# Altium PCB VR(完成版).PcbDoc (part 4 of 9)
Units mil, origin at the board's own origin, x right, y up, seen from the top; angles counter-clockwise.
Board outline 2839.68 x 2020.7 mil, 6 copper layers (TOP, GND02, SIN03, SIN04, PWR05, BOTTOM); 494 components, 404 nets, 7124 pads, 1123 vias.
Unrouted connection lines stored in the file: 10.
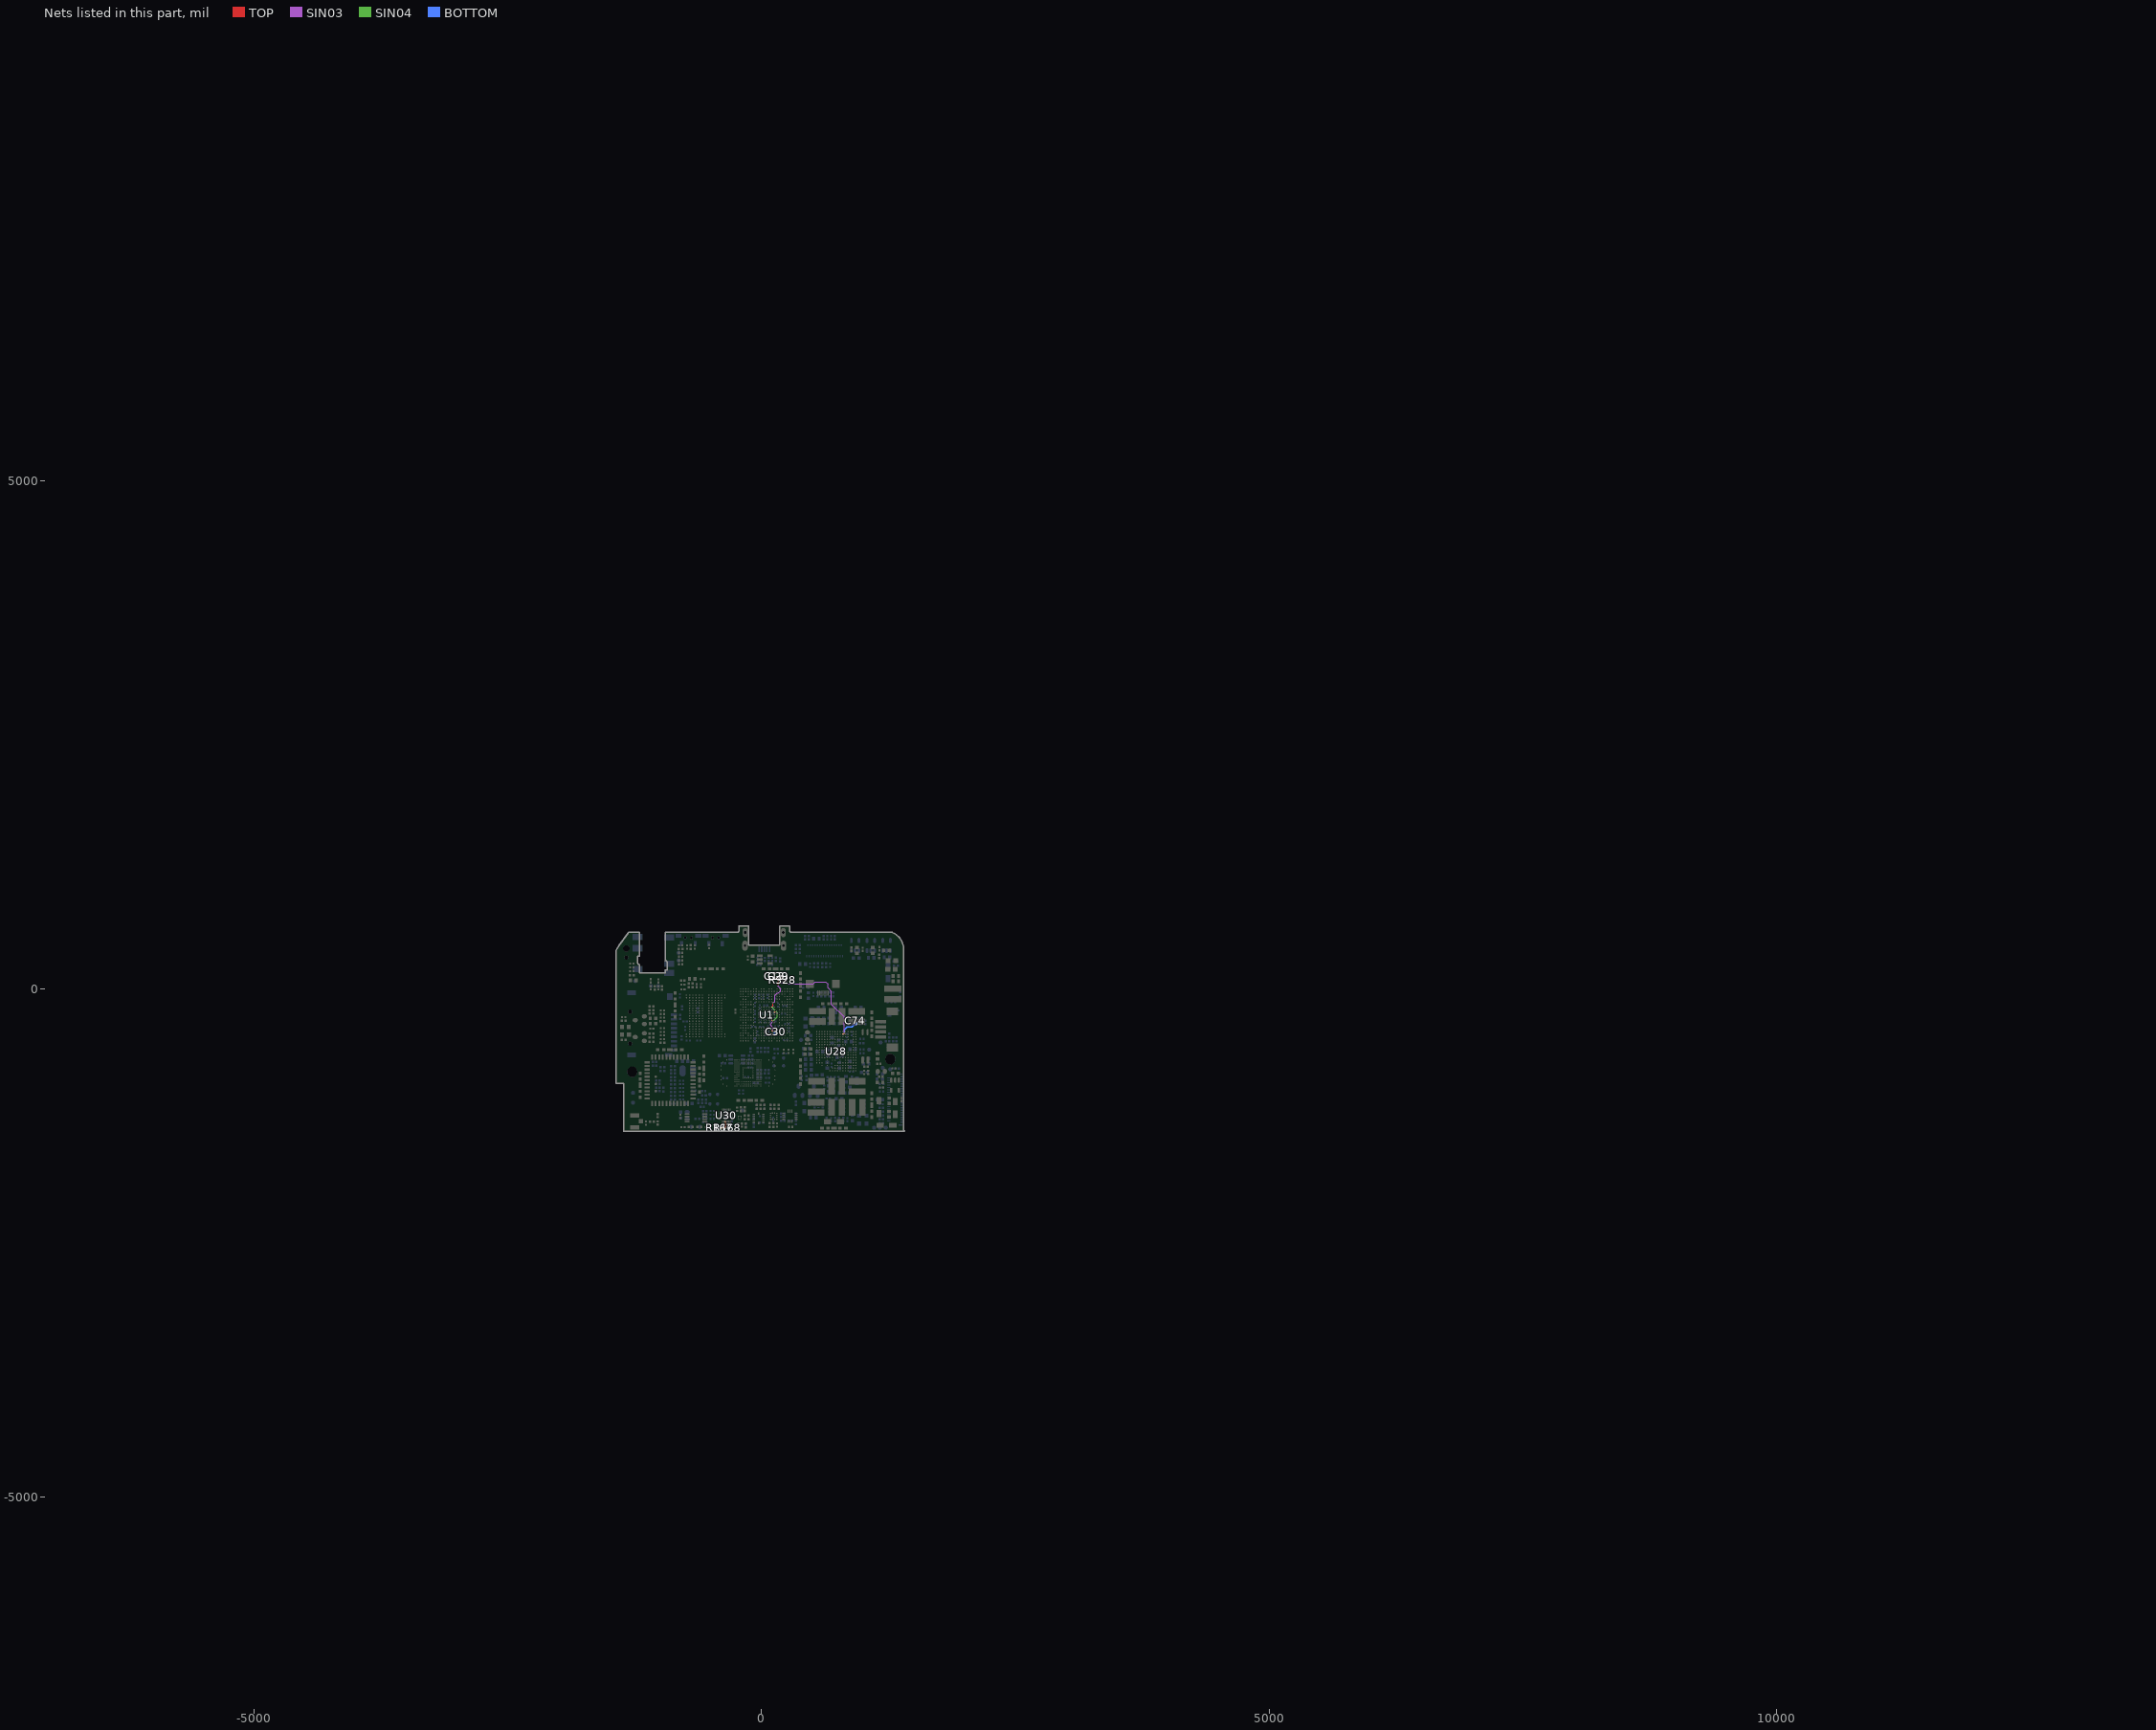
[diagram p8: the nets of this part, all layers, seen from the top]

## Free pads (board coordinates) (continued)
  round 6 on Drill Drawing: 1(6975.12,-691.2) 1(6975.12,-691.2) 1(6975.12,-656.2) 1(6995.12,-691.2) 1(7002.62,-691.2) 1(7007.12,-678.95) 1(7015.12,-656.2) 1(7015.12,-656.2) 1(7023.12,-678.95) 1(7027.62,-691.2) 1(7035.12,-656.2) 1(7045.12,-691.2) 1(7045.12,-675.45) 1(7045.12,-675.45) 1(7045.12,-675.45) 1(7055.12,-656.2) 1(7059.93,-2776.59) 1(7059.93,-2776.59) 1(7059.93,-2741.59) 1(7065.12,-691.2) 1(7065.12,-691.2) 1(7065.12,-673.12) 1(7065.12,-656.2) 1(7065.12,-656.2) 1(7077.12,-673.12) 1(7079.93,-2776.59) 1(7085.12,-691.2) 1(7085.12,-656.2) 1(7087.43,-2776.59) 1(7091.93,-2764.34) 1(7095.12,-691.2) 1(7095.12,-674.28) 1(7095.12,-656.2) 1(7095.12,-656.2) 1(7099.93,-2741.59) 1(7099.93,-2741.59) 1(7107.62,-674.28) 1(7107.62,-674.28) 1(7107.62,-674.28) 1(7107.62,-656.2) 1(7107.62,-656.2) 1(7107.93,-2764.34) 1(7111.12,-672.53) 1(7111.12,-672.53) 1(7111.62,-657.95) 1(7111.62,-657.95) 1(7112.43,-2776.59) 1(7114.12,-669.62) 1(7114.12,-669.62) 1(7114.12,-660.28) 1(7114.12,-660.28) 1(7115.12,-691.2) 1(7115.12,-664.95) 1(7115.12,-664.95) 1(7119.93,-2741.59) 1(7129.93,-2776.59) 1(7129.93,-2760.84) 1(7129.93,-2760.84) 1(7129.93,-2760.84) 1(7139.93,-2741.59) 1(7146.46,2469.67) 1(7146.46,2689.67) 1(7146.46,2909.67) 1(7146.46,3129.67) 1(7146.46,3349.67) 1(7149.93,-2776.59) 1(7149.93,-2776.59) 1(7149.93,-2758.51) 1(7149.93,-2741.59) 1(7149.93,-2741.59) 1(7161.93,-2758.51) 1(7169.93,-2776.59) 1(7169.93,-2741.59) 1(7179.93,-2776.59) 1(7179.93,-2759.67) 1(7179.93,-2741.59) 1(7179.93,-2741.59) 1(7192.43,-2759.67) 1(7192.43,-2759.67) 1(7192.43,-2759.67) 1(7192.43,-2741.59) 1(7192.43,-2741.59) 1(7195.93,-2757.92) 1(7195.93,-2757.92) 1(7196.43,-2743.34) 1(7196.43,-2743.34) 1(7198.93,-2755.01) 1(7198.93,-2755.01) 1(7198.93,-2745.67) 1(7198.93,-2745.67) 1(7199.93,-2776.59) 1(7199.93,-2750.34) 1(7199.93,-2750.34) 1(7226.46,2449.67) 1(7226.46,2449.67) 1(7226.46,2489.67) 1(7226.46,2489.67) 1(7226.46,2669.67) 1(7226.46,2669.67) 1(7226.46,2709.67) 1(7226.46,2709.67) 1(7226.46,2889.67) 1(7226.46,2889.67) 1(7226.46,2929.67) 1(7226.46,2929.67) 1(7226.46,3109.67) 1(7226.46,3109.67) 1(7226.46,3149.67) 1(7226.46,3149.67) 1(7226.46,3329.67) 1(7226.46,3329.67) 1(7226.46,3369.67) 1(7226.46,3369.67) 1(7281.46,2469.67) 1(7281.46,2469.67) 1(7281.46,2469.67) 1(7281.46,2689.67) 1(7281.46,2689.67) 1(7281.46,2689.67) 1(7281.46,2909.67) 1(7281.46,2909.67) 1(7281.46,2909.67) 1(7281.46,3129.67) 1(7281.46,3129.67) 1(7281.46,3129.67) 1(7281.46,3349.67) 1(7281.46,3349.67) 1(7281.46,3349.67) 1(7376.96,2434.88) 1(7376.96,2484.88) 1(7376.96,2654.56) 1(7376.96,2704.56) 1(7376.96,2874.25) 1(7376.96,2924.25) 1(7376.96,3093.93) 1(7376.96,3143.93) 1(7376.96,3313.62) 1(7376.96,3363.62) 1(7411.96,2419.88) 1(7411.96,2639.56) 1(7411.96,2859.25) 1(7411.96,3078.93) 1(7411.96,3298.62) 1(7416.96,2524.88) 1(7416.96,2744.56) 1(7416.96,2964.25) 1(7416.96,3183.93) 1(7416.96,3403.62) 1(7449.67,-657.23) 1(7456.67,-692.23) 1(7456.67,-692.23) 1(7461.96,2419.88) 1(7461.96,2639.56) 1(7461.96,2859.25) 1(7461.96,3078.93) 1(7461.96,3298.62) 1(7464.67,-657.23) 1(7464.67,-657.23) 1(7466.96,2524.88) 1(7466.96,2744.56) 1(7466.96,2964.25) 1(7466.96,3183.93) 1(7466.96,3403.62) 1(7472.67,-692.23) 1(7472.67,-692.23) 1(7479.67,-657.23) 1(7484.46,-2732.92) 1(7488.67,-692.23) 1(7488.67,-657.23) 1(7491.46,-2767.92) 1(7491.46,-2767.92) 1(7494.67,-692.23) 1(7494.67,-657.23) 1(7499.46,-2732.92) 1(7499.46,-2732.92) 1(7500.67,-692.23) 1(7500.67,-657.23) 1(7507.46,-2767.92) 1(7507.46,-2767.92) 1(7511.96,2419.88) 1(7511.96,2639.56) 1(7511.96,2859.25) 1(7511.96,3078.93) 1(7511.96,3298.62) 1(7513.67,-692.23) 1(7513.67,-692.23) 1(7513.67,-657.23) 1(7513.67,-657.23) 1(7514.46,-2732.92) 1(7516.96,2524.88) 1(7516.96,2744.56) 1(7516.96,2964.25) 1(7516.96,3183.93) 1(7516.96,3403.62) 1(7523.46,-2767.92) 1(7523.46,-2732.92) 1(7523.67,-692.23) 1(7523.67,-692.23) 1(7523.67,-657.23) 1(7523.67,-657.23) 1(7527.67,-690.48) 1(7527.67,-690.48) 1(7527.67,-658.98) 1(7527.67,-658.98) 1(7529.46,-2767.92) 1(7529.46,-2732.92) 1(7530.67,-688.15) 1(7530.67,-688.15) 1(7530.67,-661.31) 1(7530.67,-661.31) 1(7533.17,-684.65) 1(7533.17,-684.65) 1(7533.17,-664.81) 1(7533.17,-664.81) 1(7535.17,-680.56) 1(7535.17,-680.56) 1(7535.17,-668.9) 1(7535.17,-668.9) 1(7535.46,-2767.92) 1(7535.46,-2732.92) 1(7535.67,-674.73) 1(7535.67,-674.73) 1(7543.17,-657.23) 1(7548.46,-2767.92) 1(7548.46,-2767.92) 1(7548.46,-2732.92) 1(7548.46,-2732.92) 1(7554.67,-692.23) 1(7554.67,-657.23) 1(7558.46,-2767.92) 1(7558.46,-2767.92) 1(7558.46,-2732.92) 1(7558.46,-2732.92) 1(7562.46,-2766.17) 1(7562.46,-2766.17) 1(7562.46,-2734.67) 1(7562.46,-2734.67) 1(7565.46,-2763.84) 1(7565.46,-2763.84) 1(7565.46,-2737) 1(7565.46,-2737) 1(7566.17,-657.23) 1(7566.96,2524.88) 1(7566.96,2744.56) 1(7566.96,2964.25) 1(7566.96,3183.93) 1(7566.96,3403.62) 1(7567.96,-2760.34) 1(7567.96,-2760.34) 1(7567.96,-2740.5) 1(7567.96,-2740.5) 1(7569.96,-2756.25) 1(7569.96,-2756.25) 1(7569.96,-2744.59) 1(7569.96,-2744.59) 1(7570.46,-2750.42) 1(7570.46,-2750.42) 1(7574.17,-692.23) 1(7574.17,-674.73) 1(7574.17,-657.23) 1(7577.96,-2732.92) 1(7589.46,-2767.92) 1(7589.46,-2732.92) 1(7595.17,-692.23) 1(7595.17,-674.73) 1(7595.17,-657.23) 1(7600.96,-2732.92) 1(7608.96,-2767.92) 1(7608.96,-2750.42) 1(7608.96,-2732.92) 1(7616.96,2524.88) 1(7616.96,2744.56) 1(7616.96,2964.25) 1(7616.96,3183.93) 1(7616.96,3403.62) 1(7629.96,-2767.92) 1(7629.96,-2750.42) 1(7629.96,-2732.92) 1(7681.98,-684.06) 1(7681.98,-684.06) 1(7681.98,-660.73) 1(7681.98,-660.73) 1(7684.48,-689.89) 1(7684.48,-689.89) 1(7684.48,-654.89) 1(7684.48,-654.89) 1(7689.46,-2767.92) 1(7689.46,-2767.92) 1(7689.46,-2744.59) 1(7689.46,-2744.59) 1(7689.48,-695.73) 1(7689.48,-649.06) 1(7691.96,-2773.75) 1(7691.96,-2773.75) 1(7691.96,-2738.75) 1(7691.96,-2738.75) 1(7696.96,-2779.59) 1(7696.96,-2732.92) 1(7706.98,-684.06) 1(7706.98,-667.14) 1(7706.98,-660.73) 1(7708.48,-664.23) 1(7708.48,-664.23) 1(7710.98,-661.89) 1(7710.98,-661.89) 1(7714.46,-2767.92) 1(7714.46,-2751) 1(7714.46,-2744.59) 1(7714.48,-660.73) 1(7714.48,-660.73) 1(7715.96,-2748.09) 1(7715.96,-2748.09) 1(7717.98,-661.89) 1(7717.98,-661.89) 1(7718.46,-2745.75) 1(7718.46,-2745.75) 1(7720.48,-664.23) 1(7720.48,-664.23) 1(7721.96,-2744.59) 1(7721.96,-2744.59) 1(7721.98,-684.06) 1(7721.98,-667.14) 1(7721.98,-667.14) 1(7721.98,-667.14) 1(7723.48,-664.23) 1(7723.48,-664.23) 1(7725.46,-2745.75) 1(7725.46,-2745.75) 1(7725.98,-661.89) 1(7725.98,-661.89) 1(7727.96,-2748.09) 1(7727.96,-2748.09) 1(7729.46,-2767.92) 1(7729.46,-2751) 1(7729.46,-2751) 1(7729.46,-2751) 1(7729.48,-660.73) 1(7729.48,-660.73) 1(7730.96,-2748.09) 1(7730.96,-2748.09) 1(7732.98,-661.89) 1(7732.98,-661.89) 1(7733.46,-2745.75) 1(7733.46,-2745.75) 1(7735.48,-664.23) 1(7735.48,-664.23) 1(7736.96,-2744.59) 1(7736.96,-2744.59) 1(7736.98,-684.06) 1(7736.98,-667.73) 1(7736.98,-667.73) 1(7740.46,-2745.75) 1(7740.46,-2745.75) 1(7742.96,-2748.09) 1(7742.96,-2748.09) 1(7744.46,-2767.92) 1(7744.46,-2751.59) 1(7744.46,-2751.59) 1(7750.98,-650.81) 1(7750.98,-650.81) 1(7750.98,-649.64) 1(7750.98,-649.64) 1(7751.98,-684.06) 1(7751.98,-660.73) 1(7751.98,-651.39) 1(7751.98,-651.39) 1(7751.98,-649.06) 1(7751.98,-649.06) 1(7752.98,-650.81) 1(7752.98,-650.81) 1(7752.98,-649.64) 1(7752.98,-649.64) 1(7758.46,-2734.67) 1(7758.46,-2734.67) 1(7758.46,-2733.5) 1(7758.46,-2733.5) 1(7759.46,-2767.92) 1(7759.46,-2744.59) 1(7759.46,-2735.25) 1(7759.46,-2735.25) 1(7759.46,-2732.92) 1(7759.46,-2732.92) 1(7760.46,-2734.67) 1(7760.46,-2734.67) 1(7760.46,-2733.5) 1(7760.46,-2733.5) 1(7781.98,-684.06) 1(7781.98,-649.06) 1(7789.46,-2767.92) 1(7789.46,-2732.92) 1(7814.48,-695.73) 1(7814.48,-649.06) 1(7819.48,-689.89) 1(7819.48,-689.89) 1(7819.48,-654.89) 1(7819.48,-654.89) 1(7821.96,-2779.59) 1(7821.96,-2732.92) 1(7821.98,-684.06) 1(7821.98,-684.06) 1(7821.98,-660.73) 1(7821.98,-660.73) 1(7826.96,-2773.75) 1(7826.96,-2773.75) 1(7826.96,-2738.75) 1(7826.96,-2738.75) 1(7829.46,-2767.92) 1(7829.46,-2767.92) 1(7829.46,-2744.59) 1(7829.46,-2744.59) 1(7861.81,3928.11) 1(7861.81,3928.11) 1(7861.81,3991.11) 1(7865.98,3911.11) 1(7893.15,3928.11) 1(7920.9,3928.11) 1(7927.95,3950.16) 1(7940.48,3991.11) 1(7940.48,3991.11) 1(7953.01,3950.16) 1(7960.06,3928.11) 1(7983.53,3832.51) 1(7986.66,3871.36) 1(7986.66,3871.36) 1(7987.81,3991.11) 1(7988.23,3878.71) 1(7988.23,3878.71) 1(7989.01,3864.01) 1(7989.01,3864.01) 1(7989.8,3827.26) 1(7989.8,3827.26) 1(7992.15,3883.96) 1(7992.15,3883.96) 1(7994.5,3859.81) 1(7994.5,3859.81) 1(7996.85,3824.11) 1(7996.85,3824.11) 1(7997.63,3887.11) 1(7997.63,3887.11) 1(8003.11,3824.11) 1(8003.11,3824.11) 1(8003.11,3887.11) 1(8003.11,3887.11) 1(8003.48,3928.11) 1(8003.48,3956.46) 1(8003.48,3956.46) 1(8003.48,3956.46) 1(8003.9,3857.71) 1(8003.9,3857.71) 1(8008.6,3885.01) 1(8008.6,3885.01) 1(8009.38,3827.26) 1(8009.38,3827.26) 1(8010.95,3853.51) 1(8010.95,3853.51) 1(8013.3,3879.76) 1(8014.08,3832.51) 1(8014.08,3832.51) 1(8014.86,3847.21) 1(8014.86,3847.21) 1(8016.43,3839.86) 1(8016.43,3839.86) 1(8019.15,3991.11) 1(8027.41,-686.86) 1(8027.41,-651.86) 1(8033.41,-686.86) 1(8033.41,-651.86) 1(8039.41,-686.86) 1(8039.41,-651.86) 1(8043.4,3852.46) 1(8043.4,3852.46) 1(8044.18,3861.91) 1(8044.18,3861.91) 1(8044.96,3843.01) 1(8044.96,3843.01) 1(8047.31,3836.71) 1(8047.31,3836.71) 1(8047.31,3872.41) 1(8047.31,3872.41) 1(8050.41,-686.86) 1(8050.41,-651.86) 1(8050.41,-651.86) 1(8050.81,3928.11) 1(8050.81,3928.11) 1(8050.81,3960.66) 1(8050.81,3991.11) 1(8050.81,3991.11) 1(8051.23,3878.71) 1(8051.23,3878.71) 1(8052.01,3830.41) 1(8052.01,3830.41) 1(8056.71,3883.96) 1(8056.71,3883.96) 1(8057.5,3826.21) 1(8057.5,3826.21) 1(8062.98,3824.11) 1(8062.98,3824.11) 1(8063.41,-681.03) 1(8063.41,-681.03) 1(8063.7,2172.55) 1(8063.7,2172.55) 1(8063.7,2206.15) 1(8063.7,2235.55) 1(8063.7,2235.55) 1(8063.76,3887.11) 1(8063.76,3887.11) 1(8068.46,3824.11) 1(8068.46,3824.11) 1(8069.61,3960.66) 1(8070.03,3887.11) 1(8070.03,3887.11) 1(8073.95,3826.21) 1(8073.95,3826.21) 1(8075.51,3885.01) 1(8075.51,3885.01) 1(8076.41,-686.86) 1(8076.41,-651.86) 1(8076.41,-651.86) 1(8077.71,-2776.98) 1(8077.71,-2741.98) 1(8078.65,3829.36) 1(8078.65,3829.36) 1(8080.21,3881.86) 1(8082.15,3928.11) 1(8082.15,3991.11) 1(8082.56,3833.56) 1(8083.41,-686.86) 1(8083.41,-672.28) 1(8083.41,-651.86) 1(8083.41,-651.86) 1(8083.71,-2776.98) 1(8083.71,-2741.98) 1(8084.85,2235.55) 1(8084.85,2235.55) 1(8087.99,2206.15) 1(8087.99,2206.15) 1(8087.99,2206.15) 1(8089.55,2172.55) 1(8089.55,2172.55) 1(8089.71,-2776.98) 1(8089.71,-2741.98) 1(8090.34,2232.4) 1(8090.34,2232.4) 1(8091.12,2209.3) 1(8091.12,2209.3) 1(8093.47,2204.05) 1(8093.47,2204.05) 1(8093.47,2214.55) 1(8093.47,2214.55) 1(8093.47,2228.2) 1(8093.47,2228.2) 1(8095.04,2176.75) 1(8095.04,2176.75) 1(8095.04,2221.9) 1(8095.04,2221.9) 1(8095.41,-672.28) 1(8095.41,-672.28) 1(8095.41,-651.86) 1(8095.41,-651.86) 1(8098.17,2183.05) 1(8098.17,2183.05) 1(8098.17,2197.75) 1(8098.17,2197.75) 1(8099.41,-653.61) 1(8099.41,-653.61) 1(8099.74,2190.4) 1(8099.74,2190.4) 1(8099.91,-670.53) 1(8099.91,-670.53) 1(8100.71,-2776.98) 1(8100.71,-2741.98) 1(8100.71,-2741.98) 1(8102.41,-667.03) 1(8102.41,-667.03) 1(8102.41,-657.69) 1(8102.41,-657.69) 1(8103.41,-662.36) 1(8103.41,-662.36) 1(8106.4,3824.11) 1(8110.51,3638.56) 1(8113.41,-686.86) 1(8113.41,-686.86) 1(8113.41,-668.78) 1(8113.41,-651.86) 1(8113.41,-651.86) 1(8113.45,3846.16) 1(8113.71,-2771.15) 1(8113.71,-2771.15) 1(8113.81,3928.11) 1(8113.81,3958.56) 1(8113.81,3991.11) 1(8113.81,3991.11) 1(8123.57,2199.85) 1(8123.57,2199.85) 1(8123.57,2208.25) 1(8123.57,2208.25) 1(8125.14,2191.45) 1(8125.14,2191.45) 1(8125.14,2216.65) 1(8125.14,2216.65) 1(8125.42,-668.78) 1(8125.98,3887.11) 1(8125.98,3887.11) 1(8126.71,-2776.98) 1(8126.71,-2741.98) 1(8126.71,-2741.98) 1(8128.27,2184.1) 1(8128.27,2184.1) 1(8128.27,2224) 1(8128.27,2224) 1(8128.53,3575.56) 1(8128.53,3638.56) 1(8132.97,2177.8) 1(8132.97,2177.8) 1(8132.97,2230.3) 1(8132.97,2230.3) 1(8133.4,3958.56) 1(8133.4,3958.56) 1(8133.4,3958.56) 1(8133.4,3991.11) 1(8133.4,3991.11) 1(8133.42,-686.86) 1(8133.42,-651.86) 1(8133.71,-2776.98) 1(8133.71,-2762.4) 1(8133.71,-2741.98) 1(8133.71,-2741.98) 1(8138.45,2173.6) 1(8138.45,2173.6) 1(8138.45,2234.5) 1(8138.45,2234.5) 1(8138.51,3846.16) 1(8138.88,3961.71) 1(8138.88,3961.71) 1(8139.66,3987.96) 1(8139.66,3987.96) 1(8142.42,-686.86) 1(8142.42,-686.86) 1(8142.42,-651.86) 1(8142.42,-651.86) 1(8143.58,3966.96) 1(8143.58,3966.96) 1(8143.58,3983.76) 1(8143.58,3983.76) 1(8144.72,2172.55) 1(8144.72,2172.55) 1(8144.72,2235.55) 1(8144.72,2235.55) 1(8145.15,3928.11) 1(8145.15,3975.36) 1(8145.15,3975.36) 1(8145.56,3824.11) 1(8145.71,-2762.4) 1(8145.71,-2762.4) 1(8145.71,-2741.98) 1(8145.71,-2741.98) 1(8146.55,3638.56) 1(8149.71,-2743.73) 1(8149.71,-2743.73) 1(8150.21,-2760.65) 1(8150.21,-2760.65) 1(8150.99,2173.6) 1(8150.99,2173.6) 1(8150.99,2234.5) 1(8150.99,2234.5) 1(8152.42,-686.86) 1(8152.42,-686.86) 1(8152.42,-651.86) 1(8152.42,-651.86) 1(8152.71,-2757.15) 1(8152.71,-2757.15) 1(8152.71,-2747.81) 1(8152.71,-2747.81) 1(8153.71,-2752.48) 1(8153.71,-2752.48) 1(8156.42,-685.11) 1(8156.42,-685.11) 1(8156.42,-653.61) 1(8156.42,-653.61) 1(8156.47,2177.8) 1(8156.47,2177.8) 1(8156.47,2230.3) 1(8156.47,2230.3) 1(8159.42,-682.78) 1(8159.42,-682.78) 1(8159.42,-655.94) 1(8159.42,-655.94) 1(8161.17,2184.1) 1(8161.17,2184.1) 1(8161.17,2224) 1(8161.17,2224) 1(8161.92,-679.28) 1(8161.92,-679.28) 1(8161.92,-659.44) 1(8161.92,-659.44) 1(8163.71,-2776.98) 1(8163.71,-2776.98) 1(8163.71,-2758.9) 1(8163.71,-2741.98) 1(8163.71,-2741.98) 1(8163.92,-675.19) 1(8163.92,-675.19) 1(8163.92,-663.53) 1(8163.92,-663.53) 1(8164.3,2191.45) 1(8164.3,2191.45) 1(8164.3,2216.65) 1(8164.3,2216.65) 1(8164.42,-669.36) 1(8164.42,-669.36) 1(8165.87,2199.85) 1(8165.87,2199.85) 1(8165.87,2208.25) 1(8165.87,2208.25) 1(8170.38,3602.86) 1(8170.38,3602.86) 1(8170.38,3611.26) 1(8170.38,3611.26) 1(8170.92,-686.86) 1(8171.95,3594.46) 1(8171.95,3594.46) 1(8171.95,3619.66) 1(8171.95,3619.66) 1(8173.31,3824.11) 1(8173.31,3824.11) 1(8173.31,3887.11) 1(8175.08,3587.11) 1(8175.08,3587.11) 1(8175.08,3627.01) 1(8175.08,3627.01) 1(8175.42,-674.61) 1(8175.71,-2758.9) 1(8179.78,3580.81) 1(8179.78,3580.81) 1(8179.78,3633.31) 1(8179.78,3633.31) 1(8183.42,-651.86) 1(8183.42,-651.86) 1(8183.71,-2776.98) 1(8183.71,-2741.98) 1(8185.26,3576.61) 1(8185.26,3576.61) 1(8185.26,3637.51) 1(8185.26,3637.51) 1(8189.7,2235.55) 1(8191.42,-674.61) 1(8191.53,3575.56) 1(8191.53,3575.56) 1(8191.53,3638.56) 1(8191.53,3638.56) 1(8192.71,-2776.98) 1(8192.71,-2776.98) 1(8192.71,-2741.98) 1(8192.71,-2741.98) 1(8195.92,-686.86) 1(8197.8,3576.61) 1(8197.8,3576.61) 1(8197.8,3637.51) 1(8197.8,3637.51) 1(8201.92,-686.86) 1(8201.92,-651.86) 1(8201.92,-651.86) 1(8202.71,-2776.98) 1(8202.71,-2776.98) 1(8202.71,-2741.98) 1(8202.71,-2741.98) 1(8203.28,3580.81) 1(8203.28,3580.81) 1(8203.28,3633.31) 1(8203.28,3633.31) 1(8204.65,3824.11) 1(8206.71,-2775.23) 1(8206.71,-2775.23) 1(8206.71,-2743.73) 1(8206.71,-2743.73) 1(8207.72,2172.55) 1(8207.72,2235.55) 1(8207.98,3587.11) 1(8207.98,3587.11) 1(8207.98,3627.01) 1(8207.98,3627.01) 1(8209.71,-2772.9) 1(8209.71,-2772.9) 1(8209.71,-2746.06) 1(8209.71,-2746.06) 1(8211.11,3594.46) 1(8211.11,3594.46) 1(8211.11,3619.66) 1(8211.11,3619.66) 1(8212.21,-2769.4) 1(8212.21,-2769.4) 1(8212.21,-2749.56) 1(8212.21,-2749.56) 1(8212.68,3602.86) 1(8212.68,3602.86) 1(8212.68,3611.26) 1(8212.68,3611.26) 1(8214.21,-2765.31) 1(8214.21,-2765.31) 1(8214.21,-2753.65) 1(8214.21,-2753.65) 1(8214.71,-2759.48) 1(8214.71,-2759.48) 1(8221.21,-2776.98) 1(8224.92,-686.86) 1(8224.92,-686.86) 1(8224.92,-651.86) 1(8225.71,-2764.73) 1(8225.74,2235.55) 1(8230.92,-671.11) 1(8230.92,-671.11) 1(8231.42,-665.86) 1(8231.42,-665.86) 1(8231.92,-676.36) 1(8231.92,-676.36) 1(8233.42,-679.86) 1(8233.42,-679.86) 1(8233.42,-660.03) 1(8233.42,-660.03) 1(8233.71,-2741.98) 1(8233.71,-2741.98) 1(8235.92,-656.53) 1(8235.92,-656.53) 1(8236.31,3824.11) 1(8236.31,3824.11) 1(8236.31,3856.66) 1(8236.31,3887.11) 1(8236.31,3887.11) 1(8236.42,-683.36) 1(8236.42,-683.36) 1(8238.86,3575.56) 1(8238.86,3601.81) 1(8238.86,3638.56) 1(8238.86,3638.56) 1(8239.03,3936.51) 1(8239.42,-653.61) 1(8239.42,-653.61) 1(8239.92,-685.69) 1(8239.92,-685.69) 1(8241.71,-2764.73) 1(8242.16,3975.36) 1(8242.16,3975.36) 1(8243.42,-686.86) 1(8243.42,-686.86) 1(8243.73,3982.71) 1(8243.73,3982.71) 1(8243.92,-651.86) 1(8243.92,-651.86) 1(8244.51,3968.01) 1(8244.51,3968.01) 1(8245.3,3931.26) 1(8245.3,3931.26) 1(8246.21,-2776.98) 1(8246.92,-686.86) 1(8246.92,-686.86) 1(8247.65,3987.96) 1(8247.65,3987.96) 1(8247.92,-651.86) 1(8247.92,-651.86) 1(8250,3963.81) 1(8250,3963.81) 1(8250.42,-685.69) 1(8250.42,-685.69) 1(8251.42,-653.03) 1(8251.42,-653.03) 1(8252.21,-2776.98) 1(8252.21,-2741.98) 1(8252.21,-2741.98) 1(8252.35,3928.11) 1(8252.35,3928.11) 1(8252.7,2235.55) 1(8253.13,3991.11) 1(8253.13,3991.11) 1(8253.42,-683.94) 1(8253.42,-683.94) 1(8254.42,-654.78) 1(8255.11,3856.66) 1(8255.92,-681.61) 1(8257.66,3601.81) 1(8257.66,3601.81) 1(8257.66,3638.56) 1(8257.66,3638.56) 1(8258.61,3928.11) 1(8258.61,3928.11) 1(8258.61,3991.11) 1(8258.61,3991.11) 1(8259.4,3961.71) 1(8259.4,3961.71) 1(8263.42,-686.86) 1(8263.42,-686.86) 1(8263.42,-668.78) 1(8263.42,-651.86) 1(8263.42,-651.86) 1(8263.93,3635.41) 1(8263.93,3635.41) 1(8264.1,3989.01) 1(8264.1,3989.01) 1(8264.71,3604.96) 1(8264.71,3604.96) 1(8264.88,3931.26) 1(8264.88,3931.26) 1(8266.45,3957.51) 1(8266.45,3957.51) 1(8267.65,3824.11) 1(8267.65,3887.11) 1(8268.63,3611.26) 1(8268.63,3611.26) 1(8268.63,3628.06) 1(8268.63,3628.06) 1(8268.8,3983.76) 1(8269.58,3936.51) 1(8269.58,3936.51) 1(8270.2,3619.66) 1(8270.2,3619.66) 1(8270.36,3951.21) 1(8270.36,3951.21) 1(8270.72,2172.55) 1(8270.72,2235.55) 1(8271.93,3943.86) 1(8271.93,3943.86) 1(8275.21,-2776.98) 1(8275.21,-2776.98) 1(8275.21,-2741.98) 1(8275.42,-668.78) 1(8281.21,-2761.23) 1(8281.21,-2761.23) 1(8281.71,-2755.98) 1(8281.71,-2755.98) 1(8282.21,-2766.48) 1(8282.21,-2766.48) 1(8283.42,-686.86) 1(8283.42,-651.86) 1(8283.71,-2769.98) 1(8283.71,-2769.98) 1(8283.71,-2750.15) 1(8283.71,-2750.15) 1(8286.21,-2746.65) 1(8286.21,-2746.65) 1(8286.71,-2773.48) 1(8286.71,-2773.48) 1(8288.74,2235.55) 1(8289.71,-2743.73) 1(8289.71,-2743.73) 1(8290.21,-2775.81) 1(8290.21,-2775.81) 1(8293.71,-2776.98) 1(8293.71,-2776.98) 1(8294.21,-2741.98) 1(8294.21,-2741.98) 1(8297.21,-2776.98) 1(8297.21,-2776.98) 1(8298.21,-2741.98) 1(8298.21,-2741.98) 1(8300.46,3991.11) 1(8300.71,-2775.81) 1(8300.71,-2775.81) 1(8301.71,-2743.15) 1(8301.71,-2743.15) 1(8303.71,-2774.06) 1(8303.71,-2774.06) 1(8304.71,-2744.9) 1(8306.21,-2771.73) 1(8312.57,2199.85) 1(8312.57,2199.85) 1(8312.57,2208.25) 1(8312.57,2208.25) 1(8313.41,3823.06) 1(8313.41,3823.06) 1(8313.41,3825.16) 1(8313.41,3825.16) 1(8313.41,3851.41) 1(8313.41,3851.41) 1(8313.41,3853.51) 1(8313.41,3853.51) 1(8313.71,-2776.98) 1(8313.71,-2776.98) 1(8313.71,-2758.9) 1(8313.71,-2741.98) 1(8313.71,-2741.98) 1(8314.14,2191.45) 1(8314.14,2191.45) 1(8314.14,2216.65) 1(8314.14,2216.65) 1(8314.98,3822.01) 1(8314.98,3822.01) 1(8314.98,3826.21) 1(8314.98,3826.21) 1(8314.98,3850.36) 1(8314.98,3850.36) 1(8314.98,3854.56) 1(8314.98,3854.56) 1(8316.55,3823.06) 1(8316.55,3823.06) 1(8316.55,3825.16) 1(8316.55,3825.16) 1(8316.55,3851.41) 1(8316.55,3851.41) 1(8316.55,3853.51) 1(8316.55,3853.51) 1(8317.27,2184.1) 1(8317.27,2184.1) 1(8317.27,2224) 1(8317.27,2224) 1(8318.48,3928.11) 1(8318.48,3991.11) 1(8321.97,2177.8) 1(8321.97,2177.8) 1(8321.97,2230.3) 1(8321.97,2230.3) 1(8325.71,-2758.9) 1(8327.45,2173.6) 1(8327.45,2173.6) 1(8327.45,2234.5) 1(8327.45,2234.5) 1(8333.71,-2776.98) 1(8333.71,-2741.98) 1(8333.72,2172.55) 1(8333.72,2172.55) 1(8333.72,2235.55) 1(8333.72,2235.55) 1(8336.5,3991.11) 1(8339.99,2173.6) 1(8339.99,2173.6) 1(8339.99,2234.5) 1(8339.99,2234.5) 1(8345.47,2177.8) 1(8345.47,2177.8) 1(8345.47,2230.3) 1(8345.47,2230.3) 1(8350.17,2184.1) 1(8350.17,2184.1) 1(8350.17,2224) 1(8350.17,2224) 1(8353.3,2191.45) 1(8353.3,2191.45) 1(8353.3,2216.65) 1(8353.3,2216.65) 1(8354.87,2199.85) 1(8354.87,2199.85) 1(8354.87,2208.25) 1(8354.87,2208.25) 1(8359.96,3824.11) 1(8359.96,3887.11) 1(8359.96,3887.11) 1(8361.9,3928.11) 1(8364.08,3583.96) 1(8367.21,3622.81) 1(8367.21,3622.81) 1(8368.78,3630.16) 1(8368.78,3630.16) 1(8368.95,3950.16) 1(8369.56,3615.46) 1(8369.56,3615.46) 1(8370.35,3578.71) 1(8370.35,3578.71) 1(8372.7,3635.41) 1(8372.7,3635.41) 1(8375.05,3611.26) 1(8375.05,3611.26) 1(8376.35,2172.55) 1(8376.35,2235.55) 1(8376.35,2235.55) 1(8377.4,3575.56) 1(8377.4,3575.56) 1(8378.18,3638.56) 1(8378.18,3638.56) 1(8381.48,3991.11) 1(8381.48,3991.11) 1(8383.66,3575.56) 1(8383.66,3575.56) 1(8383.66,3638.56) 1(8383.66,3638.56) 1(8384.45,3609.16) 1(8384.45,3609.16) 1(8389.15,3636.46) 1(8389.15,3636.46) 1(8389.93,3578.71) 1(8389.93,3578.71) 1(8391.5,3604.96) 1(8391.5,3604.96) 1(8393.85,3631.21) 1(8394.01,3950.16) 1(8394.63,3583.96) 1(8394.63,3583.96) 1(8395.41,3598.66) 1(8395.41,3598.66) 1(8396,3824.11) 1(8396,3824.11) 1(8396,3887.11) 1(8396.72,2183.05) 1(8396.72,2183.05) 1(8396.98,3591.31) 1(8396.98,3591.31) 1(8401.06,3928.11) 1(8410.73,-683.69) 1(8410.73,-683.69) 1(8410.73,-660.36) 1(8410.73,-660.36) 1(8413.23,-689.52) 1(8413.23,-689.52) 1(8413.23,-654.52) 1(8413.23,-654.52) 1(8417.09,2172.55) 1(8417.09,2235.55) 1(8417.09,2235.55) 1(8418.23,-695.36) 1(8418.23,-648.69) 1(8419.83,3851.41) 1(8419.83,3851.41) 1(8419.83,3859.81) 1(8419.83,3859.81) 1(8421.4,3843.01) 1(8421.4,3843.01) 1(8421.4,3868.21) 1(8421.4,3868.21) 1(8423.71,-2776.98) 1(8423.71,-2776.98) 1(8423.71,-2753.65) 1(8423.71,-2753.65) 1(8424.53,3835.66) 1(8424.53,3835.66) 1(8424.53,3875.56) 1(8424.53,3875.56) 1(8424.9,3956.46) 1(8424.9,3956.46) 1(8425.68,3965.91) 1(8425.68,3965.91) 1(8426.21,-2782.81) 1(8426.21,-2782.81) 1(8426.21,-2747.81) 1(8426.21,-2747.81) 1(8426.46,3947.01) 1(8426.46,3947.01) 1(8428.81,3940.71) 1(8428.81,3940.71) 1(8428.81,3976.41) 1(8428.81,3976.41) 1(8429.23,3829.36) 1(8429.23,3829.36) 1(8429.23,3881.86) 1(8429.23,3881.86) 1(8431.21,-2788.65) 1(8431.21,-2741.98) 1(8432.73,3982.71) 1(8432.73,3982.71) 1(8433.51,3934.41) 1(8433.51,3934.41) 1(8434.13,3575.56) 1(8434.13,3638.56) 1(8434.71,3825.16) 1(8434.71,3825.16) 1(8434.71,3886.06) 1(8434.71,3886.06) 1(8438.21,3987.96) 1(8438.21,3987.96) 1(8439,3930.21) 1(8439,3930.21) 1(8440.98,3824.11) 1(8440.98,3824.11) 1(8440.98,3887.11) 1(8440.98,3887.11) 1(8441.73,-672.02) 1(8441.73,-672.02) 1(8442.73,-676.69) 1(8442.73,-676.69) 1(8442.73,-667.36) 1(8442.73,-667.36) 1(8443.53,3575.56) 1(8443.53,3638.56) 1(8444.48,3928.11) 1(8444.48,3928.11) 1(8444.73,-680.77) 1(8444.73,-680.77) 1(8444.73,-663.27) 1(8444.73,-663.27) 1(8445.26,3991.11) 1(8445.26,3991.11) 1(8447.25,3825.16) 1(8447.25,3825.16) 1(8447.25,3886.06) 1(8447.25,3886.06) 1(8447.73,-683.11) 1(8447.73,-683.11) 1(8447.73,-660.94) 1(8447.73,-660.94) 1(8449.96,3928.11) 1(8449.96,3928.11) 1(8450.73,-683.69) 1(8450.73,-683.69) 1(8450.73,-660.36) 1(8450.73,-660.36) 1(8451.53,3991.11) 1(8451.53,3991.11) 1(8452.73,3829.36) 1(8452.73,3829.36) 1(8452.73,3881.86) 1(8452.73,3881.86) 1(8452.93,3575.56) 1(8452.93,3638.56) 1(8453.73,-683.11) 1(8453.73,-683.11) 1(8453.73,-660.94) 1(8453.73,-660.94) 1(8454.71,-2765.31) 1(8454.71,-2765.31) 1(8455.45,3930.21) 1(8455.45,3930.21) 1(8455.71,-2769.98) 1(8455.71,-2769.98) 1(8455.71,-2760.65) 1(8455.71,-2760.65) 1(8456.73,-680.77) 1(8456.73,-680.77) 1(8456.73,-663.27) 1(8456.73,-663.27) 1(8457.01,3989.01) 1(8457.01,3989.01) 1(8457.43,3835.66) 1(8457.43,3835.66) 1(8457.43,3875.56) 1(8457.43,3875.56) 1(8457.71,-2774.06) 1(8457.71,-2774.06) 1(8457.71,-2756.56) 1(8457.71,-2756.56) 1(8458.73,-676.69) 1(8458.73,-676.69) 1(8458.73,-667.36) 1(8458.73,-667.36) 1(8459.23,-672.02) 1(8459.23,-672.02) 1(8460.15,3933.36) 1(8460.15,3933.36) 1(8460.56,3843.01) 1(8460.56,3843.01) 1(8460.56,3868.21) 1(8460.56,3868.21) 1(8460.71,-2776.4) 1(8460.71,-2776.4) 1(8460.71,-2754.23) 1(8460.71,-2754.23) 1(8461.71,3985.86) 1(8462.13,3851.41) 1(8462.13,3851.41) 1(8462.13,3859.81) 1(8462.13,3859.81) 1(8463.71,-2776.98) 1(8463.71,-2776.98) 1(8463.71,-2753.65) 1(8463.71,-2753.65) 1(8464.06,3937.56) 1(8466.71,-2776.4) 1(8466.71,-2776.4) 1(8466.71,-2754.23) 1(8466.71,-2754.23) 1(8469.71,-2774.06) 1(8469.71,-2774.06) 1(8469.71,-2756.56) 1(8469.71,-2756.56) 1(8471.71,-2769.98) 1(8471.71,-2769.98) 1(8471.71,-2760.65) 1(8471.71,-2760.65) 1(8472.21,-2765.31) 1(8472.21,-2765.31) 1(8472.23,-683.69) 1(8472.23,-665.61) 1(8472.23,-648.69) 1(8474.73,-662.69) 1(8474.73,-662.69) 1(8477.23,-660.94) 1(8477.23,-660.94) 1(8481.23,-660.36) 1(8481.23,-660.36) 1(8484.23,-660.94) 1(8484.23,-660.94) 1(8485.21,-2776.98) 1(8485.21,-2758.9) 1(8485.21,-2741.98) 1(8485.96,3824.11) 1(8485.96,3887.11) 1(8485.96,3887.11) 1(8487.71,-2755.98) 1(8487.71,-2755.98) 1(8487.73,-663.27) 1(8487.73,-663.27) 1(8489.23,-683.69) 1(8489.23,-666.77) 1(8489.23,-666.77) 1(8489.3,3575.56) 1(8489.3,3575.56) 1(8489.3,3638.56) 1(8489.3,3638.56) 1(8490.21,-2754.23) 1(8490.21,-2754.23) 1(8490.25,3928.11) 1(8490.25,3952.26) 1(8490.25,3991.11) 1(8494.21,-2753.65) 1(8494.21,-2753.65) 1(8495.73,-683.69) 1(8495.73,-666.77) 1(8495.73,-660.36) 1(8497.21,-2754.23) 1(8497.21,-2754.23) 1(8497.23,-663.86) 1(8497.23,-663.86) 1(8499.73,-661.52) 1(8499.73,-661.52) 1(8500.71,-2756.56) 1(8500.71,-2756.56) 1(8502.21,-2776.98) 1(8502.21,-2760.06) 1(8502.21,-2760.06) 1(8503.23,-660.36) 1(8503.23,-660.36) 1(8503.56,3970.11) 1(8504.96,3575.56) 1(8504.96,3575.56) 1(8504.96,3638.56) 1(8504.96,3638.56) 1(8506.27,2180.95) 1(8506.73,-661.52) 1(8506.73,-661.52) 1(8508.71,-2776.98) 1(8508.71,-2760.06) 1(8508.71,-2753.65) 1(8509.23,-663.86) 1(8509.23,-663.86) 1(8509.4,2219.8) 1(8509.4,2219.8) 1(8510.21,-2757.15) 1(8510.21,-2757.15) 1(8510.73,-683.69) 1(8510.73,-666.77) 1(8510.73,-666.77) 1(8510.73,-666.77) 1(8510.97,2227.15) 1(8510.97,2227.15) 1(8511.23,3578.71) 1(8511.23,3578.71) 1(8511.23,3635.41) 1(8511.23,3635.41) 1(8511.75,2212.45) 1(8511.75,2212.45) 1(8512.23,-663.86) 1(8512.23,-663.86) 1(8512.54,2175.7) 1(8512.54,2175.7) 1(8512.71,-2754.81) 1(8512.71,-2754.81) 1(8514.73,-661.52) 1(8514.73,-661.52) 1(8514.89,2232.4) 1(8514.89,2232.4) 1(8515.93,3582.91) 1(8515.93,3582.91) 1(8515.93,3631.21) 1(8515.93,3631.21) 1(8516.21,-2753.65) 1(8516.21,-2753.65) 1(8517.24,2208.25) 1(8517.24,2208.25) 1(8518.23,-660.36) 1(8518.23,-660.36) 1(8519.59,2172.55) 1(8519.59,2172.55) 1(8519.71,-2754.81) 1(8519.71,-2754.81) 1(8519.85,3589.21) 1(8519.85,3589.21) 1(8519.85,3624.91) 1(8519.85,3624.91) 1(8520.01,3991.11) 1(8520.37,2235.55) 1(8520.37,2235.55) 1(8521.73,-661.52) 1(8521.73,-661.52) 1(8522,3824.11) 1(8522,3824.11) 1(8522,3887.11) 1(8522.21,-2757.15) 1(8522.21,-2757.15) 1(8522.98,3596.56) 1(8522.98,3596.56) 1(8522.98,3617.56) 1(8522.98,3617.56) 1(8523.71,-2776.98) 1(8523.71,-2760.06) 1(8523.71,-2760.06) 1(8523.71,-2760.06) 1(8523.76,3607.06) 1(8523.76,3607.06) 1(8524.23,-663.86) 1(8524.23,-663.86) 1(8524.71,3928.11) 1(8525.21,-2757.15) 1(8525.21,-2757.15) 1(8525.73,-683.69) 1(8525.73,-667.36) 1(8525.73,-667.36) 1(8525.85,2172.55) 1(8525.85,2172.55) 1(8525.85,2235.55) 1(8525.85,2235.55) 1(8526.64,2206.15) 1(8526.64,2206.15) 1(8527.71,-2754.81) 1(8527.71,-2754.81) 1(8531.21,-2753.65) 1(8531.21,-2753.65) 1(8531.34,2233.45) 1(8531.34,2233.45) 1(8532.12,2175.7) 1(8532.12,2175.7) 1(8533.69,2201.95) 1(8533.69,2201.95) 1(8534.71,-2754.81) 1(8534.71,-2754.81) 1(8536.04,2228.2) 1(8536.82,2180.95) 1(8536.82,2180.95) 1(8537.21,-2757.15) 1(8537.21,-2757.15) 1(8537.6,2195.65) 1(8537.6,2195.65) 1(8538.71,-2776.98) 1(8538.71,-2760.65) 1(8538.71,-2760.65) 1(8539.17,2188.3) 1(8539.17,2188.3) 1(8543.23,-695.36) 1(8543.23,-648.69) 1(8548.23,-689.52) 1(8548.23,-689.52) 1(8548.23,-654.52) 1(8548.23,-654.52) 1(8550.73,-683.69) 1(8550.73,-683.69) 1(8550.73,-660.36) 1(8550.73,-660.36) 1(8551.31,3824.11) 1(8551.31,3824.11) 1(8551.31,3856.66) 1(8551.31,3887.11) 1(8551.31,3887.11) 1(8553.86,3575.56) 1(8553.86,3575.56) 1(8553.86,3608.11) 1(8553.86,3638.56) 1(8553.86,3638.56) 1(8556.21,-2788.65) 1(8556.21,-2741.98) 1(8561.08,3928.11) 1(8561.08,3991.11) 1(8561.21,-2782.81) 1(8561.21,-2782.81) 1(8561.21,-2747.81) 1(8561.21,-2747.81) 1(8563.71,-2776.98) 1(8563.71,-2776.98) 1(8563.71,-2753.65) 1(8563.71,-2753.65) 1(8570.11,3856.66) 1(8570.48,3928.11) 1(8570.48,3991.11) 1(8572.66,3608.11) 1(8576.32,2172.55) 1(8576.32,2235.55) 1(8579.88,3928.11) 1(8579.88,3991.11) 1(8582.65,3824.11) 1(8582.65,3887.11) 1(8585.2,3575.56) 1(8585.2,3638.56) 1(8585.72,2172.55) 1(8585.72,2235.55) 1(8595.12,2172.55) 1(8595.12,2235.55) 1(8615.46,3928.11) 1(8615.46,3991.11) 1(8615.46,3991.11) 1(8631.49,2172.55) 1(8631.49,2172.55) 1(8631.49,2235.55) 1(8631.49,2235.55) 1(8647.15,2172.55) 1(8647.15,2172.55) 1(8647.15,2235.55) 1(8647.15,2235.55) 1(8651.5,3928.11) 1(8651.5,3928.11) 1(8651.5,3991.11) 1(8653.42,2175.7) 1(8653.42,2175.7) 1(8653.42,2232.4) 1(8653.42,2232.4) 1(8658.12,2179.9) 1(8658.12,2179.9) 1(8658.12,2228.2) 1(8658.12,2228.2) 1(8662.04,2186.2) 1(8662.04,2186.2) 1(8662.04,2221.9) 1(8662.04,2221.9) 1(8665.17,2193.55) 1(8665.17,2193.55) 1(8665.17,2214.55) 1(8665.17,2214.55) 1(8665.95,2204.05) 1(8665.95,2204.05) 1(8676.11,3956.46) 1(8676.11,3956.46) 1(8676.11,3963.81) 1(8676.11,3963.81) 1(8677.68,3948.06) 1(8677.68,3948.06) 1(8677.68,3970.11) 1(8677.68,3970.11) 1(8680.81,3940.71) 1(8680.81,3940.71) 1(8680.81,3977.46) 1(8680.81,3977.46) 1(8685.51,3934.41) 1(8685.51,3934.41) 1(8685.51,3983.76) 1(8685.51,3983.76) 1(8690.21,3987.96) 1(8690.21,3987.96) 1(8691,3930.21) 1(8691,3930.21) 1(8696.05,2172.55) 1(8696.05,2172.55) 1(8696.05,2205.1) 1(8696.05,2235.55) 1(8696.05,2235.55) 1(8696.48,3991.11) 1(8696.48,3991.11) 1(8698.83,3928.11) 1(8698.83,3928.11) 1(8701.18,3959.61) 1(8701.96,3991.11) 1(8701.96,3991.11) 1(8706.66,3930.21) 1(8706.66,3930.21) 1(8708.23,3989.01) 1(8708.23,3989.01) 1(8712.15,3934.41) 1(8712.15,3934.41) 1(8712.93,3984.81) 1(8714.85,2205.1) 1(8716.85,3940.71) 1(8716.85,3940.71) 1(8716.85,3959.61) 1(8716.85,3959.61) 1(8716.98,3911.11) 1(8727.39,2172.55) 1(8727.39,2235.55) 1(8816.85,-693.01) 1(8816.85,-678.43) 1(8816.85,-658.01) 1(8816.85,-658.01) 1(8828.85,-678.43) 1(8828.85,-678.43) 1(8828.85,-658.01) 1(8828.85,-658.01) 1(8832.85,-659.76) 1(8832.85,-659.76) 1(8833.35,-676.68) 1(8833.35,-676.68) 1(8835.85,-673.18) 1(8835.85,-673.18) 1(8835.85,-663.84) 1(8835.85,-663.84) 1(8836.85,-668.51) 1(8836.85,-668.51) 1(8841.83,-2776.59) 1(8841.83,-2762.01) 1(8841.83,-2741.59) 1(8841.83,-2741.59) 1(8846.85,-693.01) 1(8846.85,-676.09) 1(8846.85,-658.01) 1(8846.85,-658.01) 1(8853.83,-2762.01) 1(8853.83,-2762.01) 1(8853.83,-2741.59) 1(8853.83,-2741.59) 1(8857.83,-2743.34) 1(8857.83,-2743.34) 1(8858.33,-2760.26) 1(8858.33,-2760.26) 1(8859.35,-676.09) 1(8859.35,-676.09) 1(8859.35,-676.09) 1(8859.35,-658.01) 1(8859.35,-658.01) 1(8860.83,-2756.76) 1(8860.83,-2756.76) 1(8860.83,-2747.42) 1(8860.83,-2747.42) 1(8861.83,-2752.09) 1(8861.83,-2752.09) 1(8862.85,-674.34) 1(8862.85,-674.34) 1(8863.35,-659.76) 1(8863.35,-659.76) 1(8865.85,-671.43) 1(8865.85,-671.43) 1(8865.85,-662.09) 1(8865.85,-662.09) 1(8866.85,-693.01) 1(8866.85,-666.76) 1(8866.85,-666.76) 1(8871.83,-2776.59) 1(8871.83,-2759.67) 1(8871.83,-2741.59) 1(8871.83,-2741.59) 1(8876.85,-693.01) 1(8876.85,-693.01) 1(8876.85,-674.93) 1(8876.85,-658.01) 1(8876.85,-658.01) 1(8884.33,-2759.67) 1(8884.33,-2759.67) 1(8884.33,-2759.67) 1(8884.33,-2741.59) 1(8884.33,-2741.59) 1(8887.83,-2757.92) 1(8887.83,-2757.92) 1(8888.33,-2743.34) 1(8888.33,-2743.34) 1(8888.85,-674.93) 1(8890.83,-2755.01) 1(8890.83,-2755.01) 1(8890.83,-2745.67) 1(8890.83,-2745.67) 1(8891.83,-2776.59) 1(8891.83,-2750.34) 1(8891.83,-2750.34) 1(8896.85,-693.01) 1(8896.85,-658.01) 1(8901.83,-2776.59) 1(8901.83,-2776.59) 1(8901.83,-2758.51) 1(8901.83,-2741.59) 1(8901.83,-2741.59) 1(8904.35,-677.26) 1(8904.35,-677.26) 1(8904.85,-672.01) 1(8904.85,-672.01) 1(8905.35,-682.51) 1(8905.35,-682.51) 1(8906.85,-686.01) 1(8906.85,-686.01) 1(8906.85,-666.18) 1(8906.85,-666.18) 1(8909.35,-662.68) 1(8909.35,-662.68) 1(8909.85,-689.51) 1(8909.85,-689.51) 1(8912.85,-659.76) 1(8912.85,-659.76) 1(8913.35,-691.84) 1(8913.35,-691.84) 1(8913.83,-2758.51) 1(8916.85,-693.01) 1(8916.85,-693.01) 1(8917.35,-658.01) 1(8917.35,-658.01) 1(8920.35,-693.01) 1(8920.35,-693.01) 1(8921.35,-658.01) 1(8921.35,-658.01) 1(8921.83,-2776.59) 1(8921.83,-2741.59) 1(8923.85,-691.84) 1(8923.85,-691.84) 1(8924.85,-659.18) 1(8924.85,-659.18) 1(8926.85,-690.09) 1(8926.85,-690.09) 1(8927.85,-660.93) 1(8929.33,-2760.84) 1(8929.33,-2760.84) 1(8929.35,-687.76) 1(8929.83,-2755.59) 1(8929.83,-2755.59) 1(8930.33,-2766.09) 1(8930.33,-2766.09) 1(8931.83,-2769.59) 1(8931.83,-2769.59) 1(8931.83,-2749.76) 1(8931.83,-2749.76) 1(8934.33,-2746.26) 1(8934.33,-2746.26) 1(8934.83,-2773.09) 1(8934.83,-2773.09) 1(8937.83,-2743.34) 1(8937.83,-2743.34) 1(8938.33,-2775.42) 1(8938.33,-2775.42) 1(8940.85,-693.01) 1(8940.85,-658.01) 1(8941.83,-2776.59) 1(8941.83,-2776.59) 1(8942.33,-2741.59) 1(8942.33,-2741.59) 1(8945.33,-2776.59) 1(8945.33,-2776.59) 1(8946.33,-2741.59) 1(8946.33,-2741.59) 1(8946.85,-693.01) 1(8946.85,-658.01) 1(8948.83,-2775.42) 1(8948.83,-2775.42) 1(8949.83,-2742.76) 1(8949.83,-2742.76) 1(8951.83,-2773.67) 1(8951.83,-2773.67) 1(8952.83,-2744.51) 1(8952.85,-693.01) 1(8952.85,-658.01) 1(8954.33,-2771.34) 1(8965.83,-2776.59) 1(8965.83,-2741.59) 1(8966.35,-688.34) 1(8968.35,-666.76) 1(8968.35,-666.76) 1(8969.35,-662.68) 1(8969.35,-662.68) 1(8969.85,-670.84) 1(8969.85,-670.84) 1(8970.35,-691.26) 1(8970.35,-691.26) 1(8971.83,-2776.59) 1(8971.83,-2741.59) 1(8971.85,-659.76) 1(8971.85,-659.76) 1(8973.35,-673.18) 1(8973.35,-673.18) 1(8974.85,-693.01) 1(8974.85,-693.01) 1(8975.35,-658.01) 1(8975.35,-658.01) 1(8977.83,-2776.59) 1(8977.83,-2741.59) 1(8978.85,-693.01) 1(8978.85,-693.01) 1(8978.85,-658.01) 1(8978.85,-658.01) 1(8979.35,-674.34) 1(8979.35,-674.34) 1(8982.35,-659.18) 1(8982.35,-659.18) 1(8982.85,-691.26) 1(8982.85,-691.26) 1(8983.85,-676.68) 1(8983.85,-676.68) 1(8985.35,-662.09) 1(8985.85,-688.34) 1(8985.85,-688.34) 1(8986.35,-680.18) 1(8986.35,-680.18) 1(8987.35,-684.26) 1(8987.35,-684.26) 1(8991.33,-2771.92) 1(8993.33,-2750.34) 1(8993.33,-2750.34) 1(8994.33,-2746.26) 1(8994.33,-2746.26) 1(8994.83,-2754.42) 1(8994.83,-2754.42) 1(8995.33,-2774.84) 1(8995.33,-2774.84) 1(8996.83,-2743.34) 1(8996.83,-2743.34) 1(8998.33,-2756.76) 1(8998.33,-2756.76) 1(8999.83,-2776.59) 1(8999.83,-2776.59) 1(9000.33,-2741.59) 1(9000.33,-2741.59) 1(9000.85,-693.01) 1(9000.85,-658.01) 1(9003.83,-2776.59) 1(9003.83,-2776.59) 1(9003.83,-2741.59) 1(9003.83,-2741.59) 1(9004.33,-2757.92) 1(9004.33,-2757.92) 1(9006.85,-693.01) 1(9006.85,-658.01) 1(9007.33,-2742.76) 1(9007.33,-2742.76) 1(9007.83,-2774.84) 1(9007.83,-2774.84) 1(9008.83,-2760.26) 1(9008.83,-2760.26) 1(9010.33,-2745.67) 1(9010.83,-2771.92) 1(9010.83,-2771.92) 1(9011.33,-2763.76) 1(9011.33,-2763.76) 1(9012.33,-2767.84) 1(9012.33,-2767.84) 1(9012.85,-693.01) 1(9012.85,-658.01) 1(9023.35,-677.84) 1(9023.35,-677.84) 1(9023.35,-673.18) 1(9023.35,-673.18) 1(9024.35,-682.51) 1(9024.35,-682.51) 1(9024.35,-668.51) 1(9024.35,-668.51) 1(9025.83,-2776.59) 1(9025.83,-2741.59) 1(9026.35,-686.59) 1(9026.35,-686.59) 1(9026.35,-664.43) 1(9026.35,-664.43) 1(9029.35,-690.09) 1(9029.35,-690.09) 1(9029.35,-660.93) 1(9029.35,-660.93) 1(9031.83,-2776.59) 1(9031.83,-2741.59) 1(9032.85,-692.43) 1(9032.85,-692.43) 1(9032.85,-658.59) 1(9032.85,-658.59) 1(9036.85,-693.01) 1(9036.85,-693.01) 1(9036.85,-658.01) 1(9036.85,-658.01) 1(9037.83,-2776.59) 1(9037.83,-2741.59) 1(9040.85,-692.43) 1(9040.85,-692.43) 1(9040.85,-658.59) 1(9040.85,-658.59) 1(9044.35,-690.09) 1(9044.35,-690.09) 1(9044.35,-660.93) 1(9044.35,-660.93) 1(9047.35,-686.59) 1(9047.35,-686.59) 1(9047.35,-664.43) 1(9047.35,-664.43) 1(9048.33,-2761.42) 1(9048.33,-2761.42) 1(9048.33,-2756.76) 1(9048.33,-2756.76) 1(9049.33,-2766.09) 1(9049.33,-2766.09) 1(9049.33,-2752.09) 1(9049.33,-2752.09) 1(9049.35,-682.51) 1(9049.35,-682.51) 1(9049.35,-668.51) 1(9049.35,-668.51) 1(9050.35,-677.84) 1(9050.35,-677.84) 1(9050.35,-673.18) 1(9050.35,-673.18) 1(9051.33,-2770.17) 1(9051.33,-2770.17) 1(9051.33,-2748.01) 1(9051.33,-2748.01) 1(9054.33,-2773.67) 1(9054.33,-2773.67) 1(9054.33,-2744.51) 1(9054.33,-2744.51) 1(9055.35,-693.01) 1(9055.35,-658.01) 1(9055.35,-658.01) 1(9057.83,-2776.01) 1(9057.83,-2776.01) 1(9057.83,-2742.17) 1(9057.83,-2742.17) 1(9061.83,-2776.59) 1(9061.83,-2776.59) 1(9061.83,-2741.59) 1(9061.83,-2741.59) 1(9065.83,-2776.01) 1(9065.83,-2776.01) 1(9065.83,-2742.17) 1(9065.83,-2742.17) 1(9069.33,-2773.67) 1(9069.33,-2773.67) 1(9069.33,-2744.51) 1(9069.33,-2744.51) 1(9072.33,-2770.17) 1(9072.33,-2770.17) 1(9072.33,-2748.01) 1(9072.33,-2748.01) 1(9074.33,-2766.09) 1(9074.33,-2766.09) 1(9074.33,-2752.09) 1(9074.33,-2752.09) 1(9075.33,-2761.42) 1(9075.33,-2761.42) 1(9075.33,-2756.76) 1(9075.33,-2756.76) 1(9078.35,-693.01) 1(9078.35,-693.01) 1(9078.35,-658.01) 1(9080.33,-2776.59) 1(9080.33,-2741.59) 1(9080.33,-2741.59) 1(9103.33,-2776.59) 1(9103.33,-2776.59) 1(9103.33,-2741.59) 1(9202.97,2525.66) 1(9202.97,2745.35) 1(9202.97,2965.04) 1(9202.97,3184.72) 1(9202.97,3404.41) 1(9252.97,2525.66) 1(9252.97,2745.35) 1(9252.97,2965.04) 1(9252.97,3184.72) 1(9252.97,3404.41) 1(9302.97,2525.66) 1(9302.97,2745.35) 1(9302.97,2965.04) 1(9302.97,3184.72) 1(9302.97,3404.41) 1(9312.97,2415.66) 1(9312.97,2635.35) 1(9312.97,2855.03) 1(9312.97,3074.72) 1(9312.97,3294.41) 1(9352.97,2525.66) 1(9352.97,2745.35) 1(9352.97,2965.04) 1(9352.97,3184.72) 1(9352.97,3404.41) 1(9362.97,2415.66) 1(9362.97,2635.35) 1(9362.97,2855.03) 1(9362.97,3074.72) 1(9362.97,3294.41) 1(9402.97,2525.66) 1(9402.97,2745.35) 1(9402.97,2965.04) 1(9402.97,3184.72) 1(9402.97,3404.41) 1(9412.97,2415.66) 1(9412.97,2635.35) 1(9412.97,2855.03) 1(9412.97,3074.72) 1(9412.97,3294.41) 1(9462.97,2415.66) 1(9462.97,2465.66) 1(9462.97,2635.35) 1(9462.97,2685.35) 1(9462.97,2855.03) 1(9462.97,2905.03) 1(9462.97,3074.72) 1(9462.97,3124.72) 1(9462.97,3294.41) 1(9462.97,3344.41) 1(9480.86,2359.67) 1(9480.86,2359.67) 1(9480.86,2359.67) 1(9480.86,2579.67) 1(9480.86,2579.67) 1(9480.86,2579.67) 1(9480.86,2799.67) 1(9480.86,2799.67) 1(9480.86,2799.67) 1(9480.86,3019.67) 1(9480.86,3019.67) 1(9480.86,3019.67) 1(9480.86,3239.67) 1(9480.86,3239.67) 1(9480.86,3239.67) 1(9480.86,3459.67) 1(9480.86,3459.67) 1(9480.86,3459.67) 1(9535.86,2339.67) 1(9535.86,2339.67) 1(9535.86,2379.67) 1(9535.86,2379.67) 1(9535.86,2559.67) 1(9535.86,2559.67) 1(9535.86,2599.67) 1(9535.86,2599.67) 1(9535.86,2779.67) 1(9535.86,2779.67) 1(9535.86,2819.67) 1(9535.86,2819.67) 1(9535.86,2999.67) 1(9535.86,2999.67) 1(9535.86,3039.67) 1(9535.86,3039.67) 1(9535.86,3219.67) 1(9535.86,3219.67) 1(9535.86,3259.67) 1(9535.86,3259.67) 1(9535.86,3439.67) 1(9535.86,3439.67) 1(9535.86,3479.67) 1(9535.86,3479.67) 1(9616.86,2359.67) 1(9616.86,2579.67) 1(9616.86,2799.67) 1(9616.86,3019.67) 1(9616.86,3239.67) 1(9616.86,3459.67) 1(9689.44,2334.4) 1(9689.44,2334.4) 1(9689.44,2376.4) 1(9689.44,2376.4) 1(9689.44,2554.4) 1(9689.44,2554.4) 1(9689.44,2596.4) 1(9689.44,2596.4) 1(9689.44,2774.4) 1(9689.44,2774.4) 1(9689.44,2816.4) 1(9689.44,2816.4) 1(9689.44,2994.4) 1(9689.44,2994.4) 1(9689.44,3036.4) 1(9689.44,3036.4) 1(9689.44,3214.4) 1(9689.44,3214.4) 1(9689.44,3256.4) 1(9689.44,3256.4) 1(9689.44,3434.4) 1(9689.44,3434.4) 1(9689.44,3476.4) 1(9689.44,3476.4) 1(9693.36,2323.9) 1(9693.36,2323.9) 1(9693.36,2386.9) 1(9693.36,2386.9) 1(9693.36,2543.9) 1(9693.36,2543.9) 1(9693.36,2606.9) 1(9693.36,2606.9) 1(9693.36,2763.9) 1(9693.36,2763.9) 1(9693.36,2826.9) 1(9693.36,2826.9) 1(9693.36,2983.9) 1(9693.36,2983.9) 1(9693.36,3046.9) 1(9693.36,3046.9) 1(9693.36,3203.9) 1(9693.36,3203.9) 1(9693.36,3266.9) 1(9693.36,3266.9) 1(9693.36,3423.9) 1(9693.36,3423.9) 1(9693.36,3486.9) 1(9693.36,3486.9) 1(9701.19,2313.4) 1(9701.19,2397.4) 1(9701.19,2533.4) 1(9701.19,2617.4) 1(9701.19,2753.4) 1(9701.19,2837.4) 1(9701.19,2973.4) 1(9701.19,3057.4) 1(9701.19,3193.4) 1(9701.19,3277.4) 1(9701.19,3413.4) 1(9701.19,3497.4) 1(10099.31,-688) 1(10099.31,-671.08) 1(10099.31,-653) 1(10099.31,-653) 1(10111.81,-671.08) 1(10111.81,-671.08) 1(10111.81,-671.08) 1(10111.81,-653) 1(10111.81,-653) 1(10111.91,-2764.77) 1(10111.91,-2747.85) 1(10111.91,-2729.77) 1(10111.91,-2729.77) 1(10115.31,-669.33) 1(10115.31,-669.33) 1(10115.81,-654.75) 1(10115.81,-654.75) 1(10118.31,-666.42) 1(10118.31,-666.42) 1(10118.31,-657.08) 1(10118.31,-657.08) 1(10119.31,-688) 1(10119.31,-661.75) 1(10119.31,-661.75) 1(10124.41,-2747.85) 1(10124.41,-2747.85) 1(10124.41,-2747.85) 1(10124.41,-2729.77) 1(10124.41,-2729.77) 1(10127.91,-2746.1) 1(10127.91,-2746.1) 1(10128.41,-2731.52) 1(10128.41,-2731.52) 1(10129.31,-688) 1(10129.31,-688) 1(10129.31,-669.92) 1(10129.31,-653) 1(10129.31,-653) 1(10130.91,-2743.19) 1(10130.91,-2743.19) 1(10130.91,-2733.85) 1(10130.91,-2733.85) 1(10131.91,-2764.77) 1(10131.91,-2738.52) 1(10131.91,-2738.52) 1(10141.31,-669.92) 1(10141.91,-2764.77) 1(10141.91,-2764.77) 1(10141.91,-2746.69) 1(10141.91,-2729.77) 1(10141.91,-2729.77) 1(10149.31,-688) 1(10149.31,-653) 1(10153.91,-2746.69) 1(10156.31,-688) 1(10156.31,-653) 1(10156.31,-653) 1(10161.91,-2764.77) 1(10161.91,-2729.77) 1(10168.91,-2764.77) 1(10168.91,-2729.77) 1(10168.91,-2729.77) 1(10169.31,-682.17) 1(10169.31,-682.17) 1(10181.91,-2758.94) 1(10181.91,-2758.94) 1(10182.31,-688) 1(10182.31,-653) 1(10182.31,-653) 1(10186.81,-688) 1(10191.31,-675.75) 1(10194.91,-2764.77) 1(10194.91,-2729.77) 1(10194.91,-2729.77) 1(10199.31,-653) 1(10199.31,-653) 1(10199.41,-2764.77) 1(10203.91,-2752.52) 1(10207.31,-675.75) 1(10211.81,-688) 1(10211.91,-2729.77) 1(10211.91,-2729.77) 1(10213.03,2313.4) 1(10213.03,2397.4) 1(10213.03,2533.4) 1(10213.03,2617.4) 1(10213.03,2753.4) 1(10213.03,2837.4) 1(10213.03,2973.4) 1(10213.03,3057.4) 1(10213.03,3193.4) 1(10213.03,3277.4) 1(10219.31,-688) 1(10219.31,-671.08) 1(10219.31,-653) 1(10219.31,-653) 1(10219.91,-2752.52) 1(10220.86,2323.9) 1(10220.86,2323.9) 1(10220.86,2386.9) 1(10220.86,2386.9) 1(10220.86,2543.9) 1(10220.86,2543.9) 1(10220.86,2606.9) 1(10220.86,2606.9) 1(10220.86,2763.9) 1(10220.86,2763.9) 1(10220.86,2826.9) 1(10220.86,2826.9) 1(10220.86,2983.9) 1(10220.86,2983.9) 1(10220.86,3046.9) 1(10220.86,3046.9) 1(10220.86,3203.9) 1(10220.86,3203.9) 1(10220.86,3266.9) 1(10220.86,3266.9) 1(10223.82,3413.49) 1(10223.82,3497.49) 1(10224.41,-2764.77) 1(10224.78,2334.4) 1(10224.78,2334.4) 1(10224.78,2376.4) 1(10224.78,2376.4) 1(10224.78,2554.4) 1(10224.78,2554.4) 1(10224.78,2596.4) 1(10224.78,2596.4) 1(10224.78,2774.4) 1(10224.78,2774.4) 1(10224.78,2816.4) 1(10224.78,2816.4) 1(10224.78,2994.4) 1(10224.78,2994.4) 1(10224.78,3036.4) 1(10224.78,3036.4) 1(10224.78,3214.4) 1(10224.78,3214.4) 1(10224.78,3256.4) 1(10224.78,3256.4) 1(10231.65,3423.99) 1(10231.65,3423.99) 1(10231.65,3486.99) 1(10231.65,3486.99) 1(10231.81,-671.08) 1(10231.81,-671.08) 1(10231.81,-671.08) 1(10231.81,-653) 1(10231.81,-653) 1(10231.91,-2764.77) 1(10231.91,-2747.85) 1(10231.91,-2729.77) 1(10231.91,-2729.77) 1(10235.31,-669.33) 1(10235.31,-669.33) 1(10235.57,3434.49) 1(10235.57,3434.49) 1(10235.57,3476.49) 1(10235.57,3476.49) 1(10235.81,-654.75) 1(10235.81,-654.75) 1(10238.31,-666.42) 1(10238.31,-666.42) 1(10238.31,-657.08) 1(10238.31,-657.08) 1(10239.31,-688) 1(10239.31,-661.75) 1(10239.31,-661.75) 1(10244.41,-2747.85) 1(10244.41,-2747.85) 1(10244.41,-2747.85) 1(10244.41,-2729.77) 1(10244.41,-2729.77) 1(10247.91,-2746.1) 1(10247.91,-2746.1) 1(10248.31,-688) 1(10248.31,-674.58) 1(10248.31,-653) 1(10248.41,-2731.52) 1(10248.41,-2731.52) 1(10250.91,-2743.19) 1(10250.91,-2743.19) 1(10250.91,-2733.85) 1(10250.91,-2733.85) 1(10251.91,-2764.77) 1(10251.91,-2738.52) 1(10251.91,-2738.52) 1(10256.81,-664.67) 1(10260.91,-2764.77) 1(10260.91,-2751.35) 1(10260.91,-2729.77) 1(10267.31,-653) 1(10269.41,-2741.44) 1(10270.31,-688) 1(10279.91,-2729.77) 1(10282.91,-2764.77)
  round 10 on Drill Drawing: 1(7376.96,2306.4) 1(7376.96,2306.4) 1(7376.96,2306.4) 1(7376.96,2416.25) 1(7376.96,2526.09) 1(7376.96,2635.93) 1(7376.96,2745.78) 1(7376.96,2855.62) 1(7376.96,2965.46) 1(7376.96,3075.3) 1(7376.96,3185.15) 1(7376.96,3294.99) 1(7376.96,3404.83) 1(7376.96,3514.67) 1(7376.96,3514.67) 1(9463.97,2306.4) 1(9463.97,2306.4) 1(9463.97,2306.4) 1(9463.97,2416.25) 1(9463.97,2526.09) 1(9463.97,2635.93) 1(9463.97,2745.78) 1(9463.97,2855.62) 1(9463.97,2965.46) 1(9463.97,3075.3) 1(9463.97,3185.15) 1(9463.97,3294.99) 1(9463.97,3404.83) 1(9463.97,3514.67) 1(9463.97,3514.67)

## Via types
v1: diameter 14, hole 8, TOP to BOTTOM, tented both sides, 707 vias
v2: diameter 16, hole 10, TOP to BOTTOM, tented both sides, 275 vias
v3: diameter 16, hole 8, TOP to BOTTOM, tented both sides, 134 vias
v4: diameter 8, hole 8, TOP to BOTTOM, tented both sides, 3 vias
v5: diameter 10, hole 10, TOP to BOTTOM, tented both sides, 2 vias
v6: diameter 14, hole 8, TOP to BOTTOM, tented top, 1 vias
v7: diameter 14, hole 10, TOP to BOTTOM, tented both sides, 1 vias

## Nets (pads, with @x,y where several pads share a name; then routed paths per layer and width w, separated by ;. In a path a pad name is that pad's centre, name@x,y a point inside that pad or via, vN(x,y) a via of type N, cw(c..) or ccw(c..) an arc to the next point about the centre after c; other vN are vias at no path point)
AD0: R167.1 R168.2 U30.9 | length 99.7
  TOP w5: R167.1@-392.27,-1367.86 -391.27,-1366.86 R168.2@-352.27,-1366.86 -353.14,-1365.99 U30.9@-353.14,-1307.92
ALDO1: C13.1 C29.2 C30.2 C74.2 R328.2 U1.H13 U1.K14 U1.N13 U1.U13 U28.R6 | length 2123.9
  TOP w10: U1.U13@102.36,-409.45 v1(115.16,-422.25) ; U1.N13@102.36,-307.09 v1(115.16,-319.89) ; U1.H13@102.36,-179.14 115.16,-166.34 v1(115.16,-140.75) ; C13.1@127.38,106.38 C29.2@173,106.38 ; U1.K14@127.95,-230.32 v1(140.75,-217.52) ; v1(160,38) 160,61 173,74 C29.2@173,106.38 ; C29.2@173,108 C29.2@173,106.38 ; R328.2@211,106.38 C29.2@173,106.38
  TOP w12: U28.R6@802.59,-446.69 v3(815.39,-433.89)
  SIN03 w10: v1(115.16,-422.25) 115.16,-383.16 89.57,-357.57 89.57,-345.48 v1(115.16,-319.89) ; v1(115.16,-140.75) 132,-123.91 132,-63 154.87,-40.13 167.87,-40.13 188,-20 188,0 160,28 v1(160,38) 160,46 172,58 250,58 258,50 511,50 531,70 634,70 654,50 654,11 691,-26 691,-152 815.39,-276.39 v3(815.39,-433.89)
  SIN04 w10: v1(115.16,-319.89) 158,-277.04 158,-234.77 v1(140.75,-217.52) 115.16,-191.93 v1(115.16,-140.75)
  BOTTOM w12: v3(815.39,-433.89) 815.39,-401.61 843.14,-373.86 893.08,-373.86 C74.2@925.7,-341.24
  BOTTOM w15: v1(115.16,-422.25) 116.1,-422.25 134.14,-440.28 C30.2@145,-440.28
